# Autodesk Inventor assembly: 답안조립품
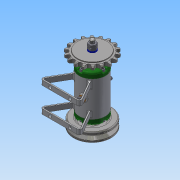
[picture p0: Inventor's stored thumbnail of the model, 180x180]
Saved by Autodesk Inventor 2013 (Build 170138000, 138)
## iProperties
Created: 2016-03
Part Number: 답안조립품
Document SubType Name: Assembly
Designer: Administrator
Author: Administrator
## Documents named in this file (16)
- C:\Users\Administrator\Desktop\460308V1026\답안조립품.iam
- C:\Users\Administrator\Desktop\460308V1026\본체.ipt
- C:\Users\Administrator\Desktop\460308V1026\V벨트풀리.ipt
- C:\Users\Administrator\Desktop\460308V1026\너트 M 8.ipt
- C:\Users\Administrator\Desktop\460308V1026\니플 M 6 x 0.75.ipt
- C:\Users\Administrator\Desktop\460308V1026\베어링 15 x 32 x 9.ipt
- C:\Users\Administrator\Desktop\460308V1026\볼트 M 6 x 8.ipt
- C:\Users\Administrator\Desktop\460308V1026\볼트 M4 x 12.ipt
- C:\Users\Administrator\Desktop\460308V1026\스프로킷.ipt
- C:\Users\Administrator\Desktop\460308V1026\스프링와셔 8.ipt
- C:\Users\Administrator\Desktop\460308V1026\오일 실 15 25 7.ipt
- C:\Users\Administrator\Desktop\460308V1026\와셔 6x11.5.ipt
- C:\Users\Administrator\Desktop\460308V1026\와셔 8x17.ipt
- C:\Users\Administrator\Desktop\460308V1026\축.ipt
- C:\Users\Administrator\Desktop\460308V1026\커버.ipt
- C:\Users\Administrator\Desktop\460308V1026\키 3 x 3 x 12.ipt
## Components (11 placed, 3 different names)
1. V벨트풀리:1
2. KS B 2023 6002 - 15 x 32 x 9:1
3. KS B 2023 6002 - 15 x 32 x 9:2
4. ISO 4762 M4 x 12:2
5. ISO 4762 M4 x 12:3
6. ISO 4762 M4 x 12:4
7. ISO 4762 M4 x 12:5
8. ISO 4762 M4 x 12:1
9. ISO 4762 M4 x 12:6
10. ISO 4762 M4 x 12:7
11. ISO 4762 M4 x 12:8
